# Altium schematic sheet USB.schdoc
size 259 x 177 mm
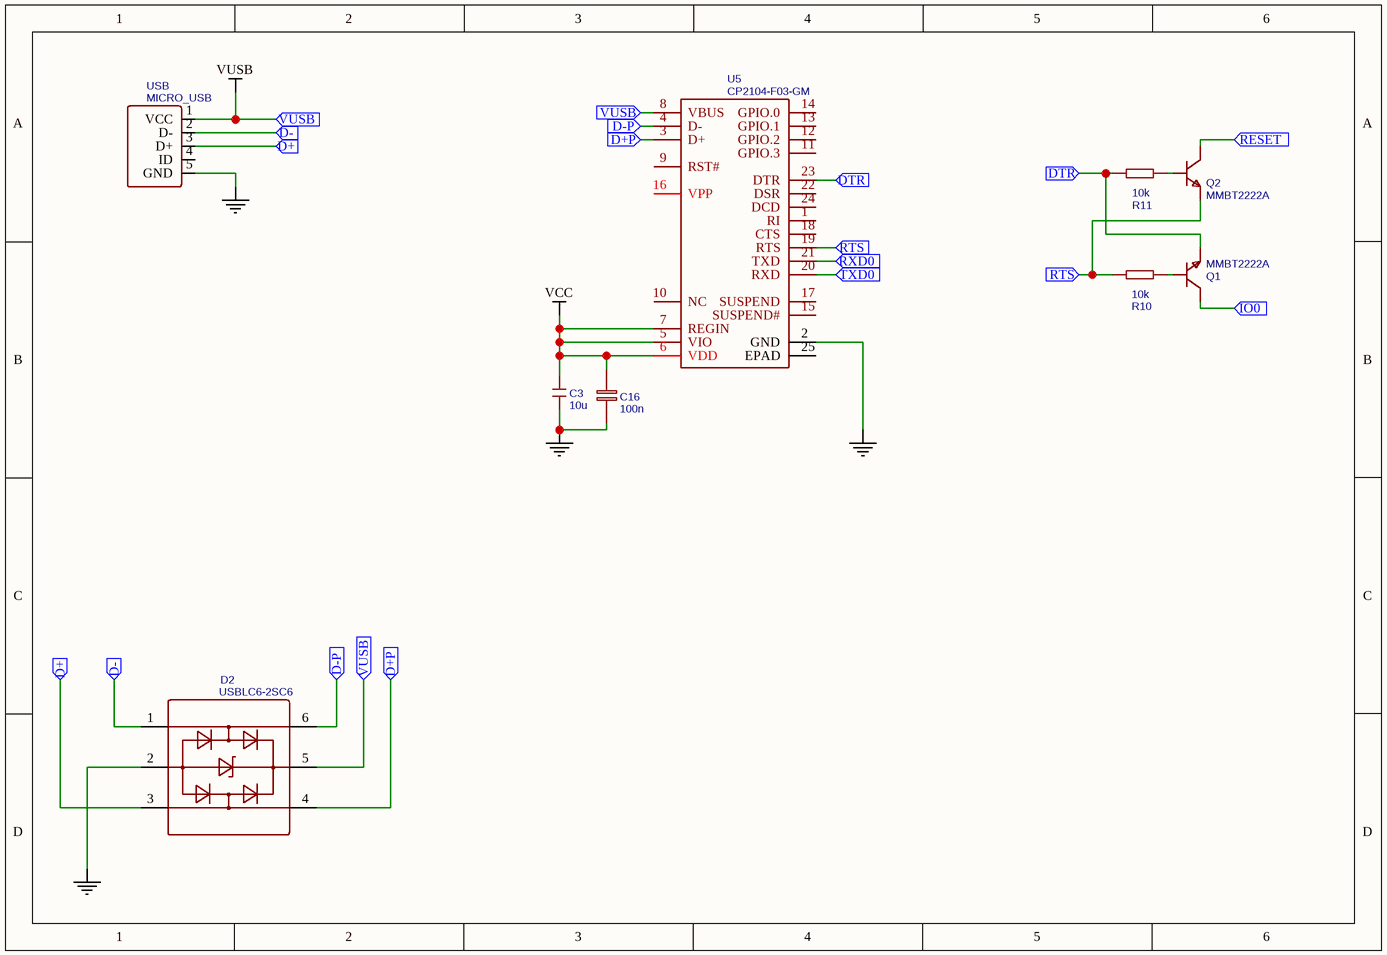
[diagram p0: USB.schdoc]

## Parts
C3  10u  [0603]
C16  100n  [0603]
D2  USBLC6-2SC6  [SOT-23-6]
Q1  MMBT2222A  [SOT-23(SOT-23-3)]
Q2  MMBT2222A  [SOT-23(SOT-23-3)]
R10  10k  [0603]
R11  10k  [0603]
U5  CP2104-F03-GM  [QFN-24_4X4X05P]
USB  MICRO_USB  [MICRO_5P_C40940]

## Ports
D+ (in), D+P (in), D- (in), D-P (in), DTR (in), IO0 (in), RESET (in), RTS (in), RXD0 (in), TXD0 (in), VUSB (in)

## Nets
GND: C3.1 C16.2 D2.2 U5.2(GND) USB.5(GND)
VCC: C3.2 C16.1 U5.5(VIO) U5.6(VDD) U5.7(REGIN)
VUSB: D2.5 U5.8(VBUS) USB.1(VCC) ; port VUSB
D+: D2.3 USB.3(D+) ; port D+
D+P: D2.4 U5.3(D+) ; port D+P
D-: D2.1 USB.2(D-) ; port D-
D-P: D2.6 U5.4(D-) ; port D-P
DTR: Q1.2(E) R11.2 U5.23(DTR) ; port DTR
IO0: Q1.3(C) ; port IO0
RESET: Q2.3(C) ; port RESET
RTS: Q2.2(E) R10.2 U5.19(RTS) ; port RTS
RXD0: U5.21(TXD) ; port RXD0
TXD0: U5.20(RXD) ; port TXD0
NetQ1_1: Q1.1(B) R10.1
NetQ2_1: Q2.1(B) R11.1

Not connected (* = marked no-connect by the designer): U5 1(RI) 9(RST#) 10(NC) 11(GPIO.3) 12(GPIO.2) 13(GPIO.1) 14(GPIO.0) 15(SUSPEND#) 16(VPP) 17(SUSPEND) 18(CTS) 22(DSR) 24(DCD) 25(EPAD); USB 4(ID)

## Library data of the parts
C3 = 10u: BOM_Manufacturer Part: GRM188R61C106MA73D; BOM_Manufacturer: MuRata
C16 = 100n: BOM_Manufacturer Part: GRM188B11E104KA01D; BOM_Manufacturer: MuRata; nameAlias: Value(F)
D2 = USBLC6-2SC6: BOM_Manufacturer: STMicroelectronics; SMT Type: Extend
Q1 Q2 = MMBT2222A: BOM_Manufacturer: SK; Contributor: LCSC
R10 R11 = 10k: BOM_Manufacturer Part: RC0603JR-0710KL; BOM_Manufacturer: YAGEO; Contributor: DangerousPrototype
U5 = CP2104-F03-GM: BOM_Manufacturer: SILICON LABS; Contributor: LCSC
USB = MICRO_USB: BOM_Manufacturer: ValuePro; BOM_Manufacturer Part: Micro USB-B 5P-Female-SMT; Contributor: garjans.miks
